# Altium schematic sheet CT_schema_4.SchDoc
size 184 x 159 mm
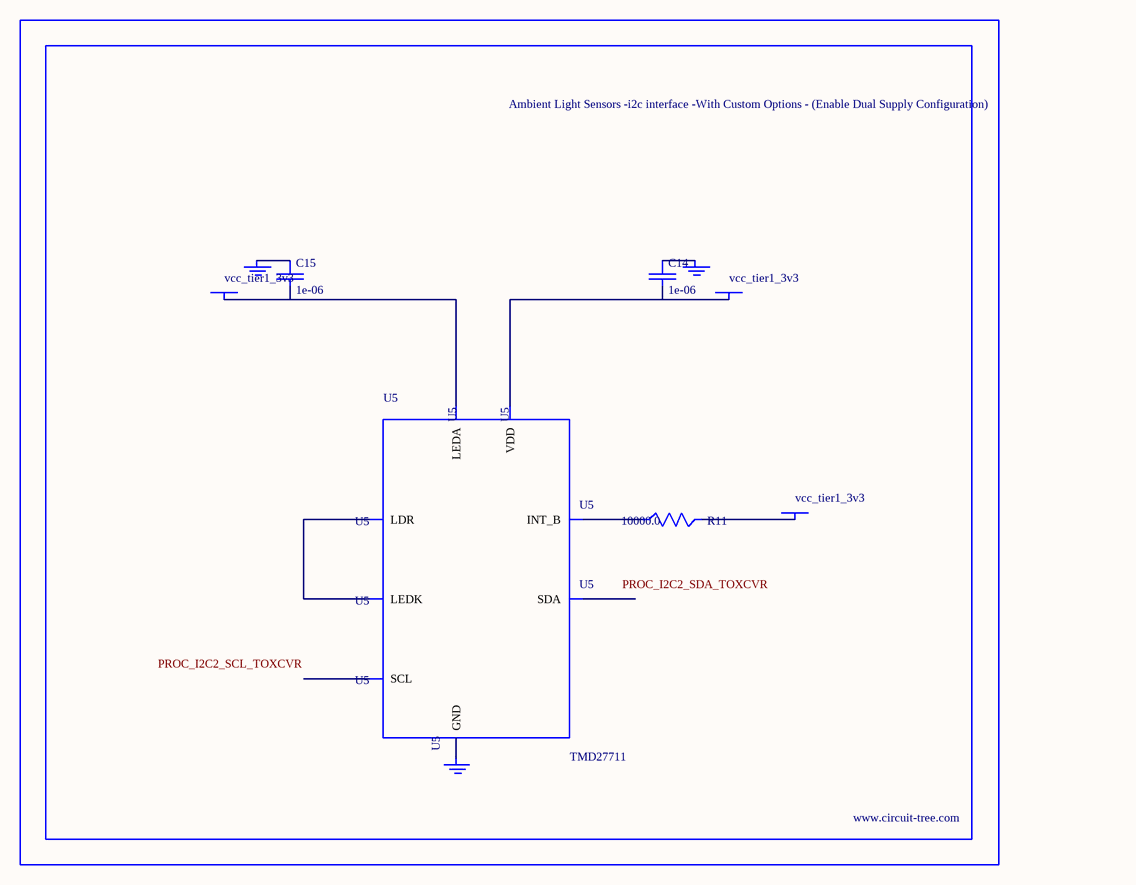
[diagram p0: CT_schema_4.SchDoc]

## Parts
BORDER3  (no value)
C14  1e-06  [C0603]
C15  1e-06  [C0603]
GND_INSTANCE_3_0  (no value)
GND_INSTANCE_3_1  (no value)
GND_INSTANCE_3_2  (no value)
POWER_INSTANCE_3_0  vcc_tier1_3v3
POWER_INSTANCE_3_1  vcc_tier1_3v3
POWER_INSTANCE_3_2  vcc_tier1_3v3
R11  10000.0  [R0603]
U5  TMD27711  [SMD-8]

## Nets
NetC14_1: C14.1 GND_INSTANCE_3_0.0(GND)
NetC14_2: C14.2 POWER_INSTANCE_3_0.0(PWR) U5.1(VDD)
NetC15_1: C15.1 GND_INSTANCE_3_1.0(GND)
NetC15_2: C15.2 POWER_INSTANCE_3_1.0(PWR) U5.4(LEDA)
NetGND_INSTANCE_3_2_0: GND_INSTANCE_3_2.0(GND) U5.3(GND)
NetPOWER_INSTANCE_3_2_0: POWER_INSTANCE_3_2.0(PWR) R11.2
NetR11_1: R11.1 U5.7(INT_B)
NetU5_5: U5.5(LEDK) U5.6(LDR)

Not connected (* = marked no-connect by the designer): U5 2(SCL) 8(SDA)

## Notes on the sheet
- Labels drawn without touching a wire or pin: PROC_I2C2_SCL_TOXCVR, PROC_I2C2_SDA_TOXCVR

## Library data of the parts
BORDER3 = BORDER_PAGE3
C14 C15 = C0603C105K3RACTU
GND_INSTANCE_3_0-GND_INSTANCE_3_2 = GND
POWER_INSTANCE_3_0-POWER_INSTANCE_3_2 = PWR
R11 = RC0603JR-0710KL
